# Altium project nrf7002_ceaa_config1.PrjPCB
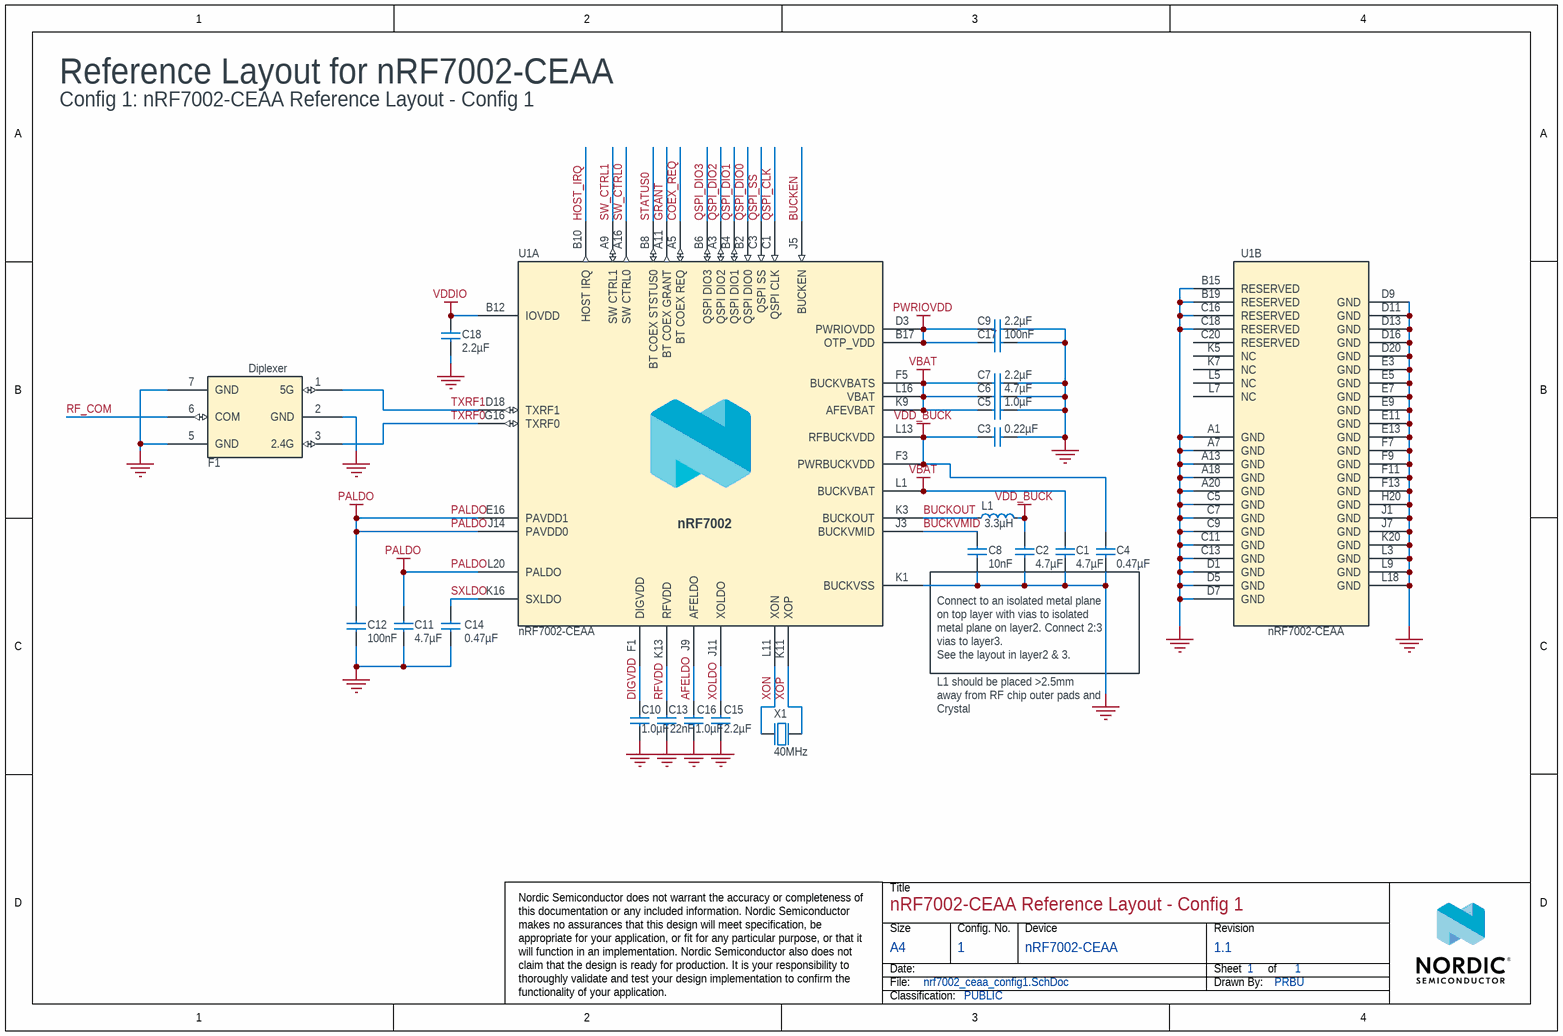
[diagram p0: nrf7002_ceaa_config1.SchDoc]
Title: nRF7002-CEAA Reference Layout -Config 1; sheettotal: 1; sheetnumber: 1; Revision: 1.1; Drawnby: PRBU; Device: nRF7002-CEAA; Config: 1; Classification: PUBLIC
1 sheet, 22 parts. Net scope: global (net labels, ports and power ports of the same name join across sheets).
Board file: nRF7002_ceaa_config1.PcbDoc

## Sheet nrf7002_ceaa_config1.SchDoc: nRF7002-CEAA Reference Layout -Config 1
size A4; PCAName: nRF7002 Reference Layout Alt. 1; BoardTitle: nRF7002 Reference Layout Alt. 1; Organization: Nordic Semiconductor; Revision: 1.1; SheetNumber: 1; SheetTotal: 1; DrawnBy: PRBU; DocumentSize: A4; RefLayoutTitle: nRF7002-CEAA Reference Layout - Config 1; Device: nRF7002-CEAA; Classification: PUBLIC

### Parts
C1  4.7µF  [CAPC1608X06L]
C2  4.7µF  [CAPC1608X06L]
C3  0.22µF  [CAPC0603X03L_C]
C4  0.47µF  [CAPC0603X03L_C]
C5  1.0µF  [CAPC1005X04L]
C6  4.7µF  [CAPC1608X06L]
C7  2.2µF  [CAPC1608X06L]
C8  10nF  [CAPC0603X03L_C]
C9  2.2µF  [CAPC1005X04L]
C10  1.0µF  [CAPC1005X04L]
C11  4.7µF  [CAPC1608X06L]
C12  100nF  [CAPC0603X03L_C]
C13  22nF  [CAPC0603X03L_C]
C14  0.47µF  [CAPC0603X03L_C]
C15  2.2µF  [CAPC0603X03L_C]
C16  1.0µF  [CAPC1005X04L]
C17  100nF  [CAPC0603X03L_C]
C18  2.2µF  [CAPC1005X04L]
F1  LFD_5G_Diplexer  [CAF-50P160X80-6N]  (value not drawn)
L1  3.3µH  [INDC2520X10N]
U1  nRF7002-CEAA  [nRF7002_WLCSP_R2]  (parts A,B of 2)
X1  40MHz  [BT-XTAL_1612]

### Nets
GND: C1.1 C2.1 C3.1 C4.1 C5.1 C6.1 C7.1 C8.1 C9.1 C10.2 C11.1 C12.1 C13.1 C14.1 C15.1 C16.1 C17.1 C18.1 F1.2(GND) F1.5(GND) F1.7(GND) U1.A1(GND) U1.A7(GND) U1.A13(GND) U1.A18(GND) U1.A20(GND) U1.B15(RESERVED) U1.B19(RESERVED) U1.C5(GND) U1.C7(GND) U1.C9(GND) U1.C11(GND) U1.C13(GND) U1.C16(RESERVED) U1.C18(RESERVED) U1.D1(GND) U1.D5(GND) U1.D7(GND) U1.D9(GND) U1.D11(GND) U1.D13(GND) U1.D16(GND) U1.D20(GND) U1.E3(GND) U1.E5(GND) U1.E7(GND) U1.E9(GND) U1.E11(GND) U1.E13(GND) U1.F7(GND) U1.F9(GND) U1.F11(GND) U1.F13(GND) U1.H20(GND) U1.J1(GND) U1.J7(GND) U1.K1(BUCKVSS) U1.K20(GND) U1.L3(GND) U1.L9(GND) U1.L18(GND) X1.2(GND) X1.4(GND)
PALDO: C11.2 C12.2 U1.E16(PAVDD1) U1.J14(PAVDD0) U1.L20(PALDO)
PWRIOVDD: C9.2 C17.2 U1.B17(OTP_VDD) U1.D3(PWRIOVDD)
VBAT: C1.2 C5.2 C6.2 C7.2 U1.F5(BUCKVBATS) U1.K9(AFEVBAT) U1.L1(BUCKVBAT) U1.L16(VBAT)
VDD_BUCK: C2.2 C3.2 C4.2 L1.2 U1.F3(PWRBUCKVDD) U1.L13(RFBUCKVDD)
VDDIO: C18.2 U1.B12(IOVDD)
AFELDO: C16.2 U1.J9(AFELDO)
BUCKEN: U1.J5(BUCKEN)
BUCKOUT: L1.1 U1.K3(BUCKOUT)
BUCKVMID: C8.2 U1.J3(BUCKVMID)
COEX_REQ: U1.A5(BT_COEX_REQ)
DIGVDD: C10.1 U1.F1(DIGVDD)
GRANT: U1.A11(BT_COEX_GRANT)
HOST_IRQ: U1.B10(HOST_IRQ)
QSPI_CLK: U1.C1(QSPI_CLK)
QSPI_DIO0: U1.B2(QSPI_DIO0)
QSPI_DIO1: U1.B4(QSPI_DIO1)
QSPI_DIO2: U1.A3(QSPI_DIO2)
QSPI_DIO3: U1.B6(QSPI_DIO3)
QSPI_SS: U1.C3(QSPI_SS)
RF_COM: F1.6(COM)
RFVDD: C13.2 U1.K13(RFVDD)
STATUS0: U1.B8(BT_COEX_STSTUS0)
SW_CTRL0: U1.A16(SW_CTRL0)
SW_CTRL1: U1.A9(SW_CTRL1)
SXLDO: C14.2 U1.K16(SXLDO)
TXRF0: F1.3(2.4G) U1.G16(TXRF0)
TXRF1: F1.1(5G) U1.D18(TXRF1)
XOLDO: C15.2 U1.J11(XOLDO)
XON: U1.L11(XON) X1.1(inp)
XOP: U1.K11(XOP) X1.3(out)

Not connected (* = marked no-connect by the designer): U1 C20(RESERVED) K5(NC) K7(NC) L5(NC) L7(NC)

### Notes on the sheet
- (near F1) Diplexer
- Connect to an isolated metal plane
  on top layer with vias to isolated
  metal plane on layer2. Connect 2:3
  vias to layer3.
  See the layout in layer2 & 3.
- L1 should be placed >2.5mm
  away from RF chip outer pads and Crystal

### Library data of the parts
C1 C2 C6 C11 = C0603-4µ7-25V-X6S-GRM188C81E475KE11: Capacitor, Ceramic, X6S 0603,±10%, 25V; Manufacturer: Murata; Manufacturer Part Number: GRM188C81E475KE11D; Pad Count: 2
C3 = C0201-220n-10V-X5R-GRM033R61A224KE90: Capacitor, Ceramic, X5R 0201, ±10%, 10V; Manufacturer: Murata; Manufacturer Part Number: GRM033R61A224KE90D; Pad Count: 2
C4 C14 = C0201-470n-6.3V-X5R-GRM033R60J474KE90: Capacitor, Ceramic, X5R 0201,±10%, 6.3V; Manufacturer: Murata; Manufacturer Part Number: GRM033R60J474KE90D; Pad Count: 2
C5 = C0402-1µ0-35V-X5R-GRM155R6YA105KE11: Capacitor, Ceramic, X5R 0402,±10%, 35V; Manufacturer: Murata; Manufacturer Part Number: GRM155R6YA105KE11D; Pad Count: 2
C7 = C0603-2µ2-16V-X7S-GRM188C71C225KE11: Capacitor, Ceramic, X7S 0603,±10%,16V; Manufacturer: Murata; Manufacturer Part Number: GRM188C71C225KE11D; Pad Count: 2
C8 = C0201-10n-16V-X7R-GRM033R71C103KE14: Capacitor, Ceramic, X7R 0201,±10%, 16V; Manufacturer: Murata; Manufacturer Part Number: GRM033R71C103KE14D; Pad Count: 2
C9 C18 = C0402-2µ2-25V-X5R-GRM155R61E225KE11: Capacitor, Ceramic, X5R 0402,±10%, 25V; Manufacturer: Murata; Manufacturer Part Number: GRM155R61E225KE11D; Pad Count: 2
C10 = C0402-1µ0-16V-X6S-GRM155C81C105KE11J: Capacitor, Ceramic, X6S 0402,±10%, 16V; Manufacturer: Murata; Pad Count: 2
C12 C17 = C0201-100n-16V-X7S-GRM033C71C104KE14: Capacitor, Ceramic, X7S 0201,±10%, 16V; Manufacturer: Murata; Manufacturer Part Number: GRM033C71C104KE14D; Pad Count: 2
C13 = C0201-22n-10V-X5R-GRM033R61A223KE84: Capacitor, Ceramic, X5R 0201,±10%, 10V; Manufacturer: Murata; Manufacturer Part Number: GRM033R61A223KE84D; Pad Count: 2
C15 = C0201-2µ2-10V-X5R-GRM033R61A225KE47: Capacitor, Ceramic, X5R 0201,±10%, 10V; Manufacturer: Murata; Manufacturer Part Number: GRM033R61A225KE47D; Pad Count: 2
C16 = C0402-1µ0-10V-X7S-GRM155C71A105KE11: Capacitor, Ceramic, X7S 0402,±10%,10V; Manufacturer: Murata; Manufacturer Part Number: GRM155C71A105KE11D; Pad Count: 2
F1 = LFD182G45DCHD277: Signal Conditioning 2.4GHz and 5GHz Diplexer; Manufacturer: Murata; Pad Count: 6
L1 = L1008-3µ3-LQM2HPN3R3MGCL: Inductor, 1A, ±20%, 200mOhm; Manufacturer: Murata; Pad Count: 2
U1 = nRF7002-CEAA: Wi-Fi Dual Band Companion chip WLCSP; Manufacturer: Nordic Semiconductor; Pad Count: 49
X1 = XTAL_SMD1612_40MHz_8p_40_85: XTAL SMD 1612, 40MHz, Cl=8pF, Total Tol: ±10ppm, -40-85C; Manufacturer: Abracon Corporation; Manufacturer Part Number: ABM12W-40.0000MHZ-8-D1X-T3; Pad Count: 4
